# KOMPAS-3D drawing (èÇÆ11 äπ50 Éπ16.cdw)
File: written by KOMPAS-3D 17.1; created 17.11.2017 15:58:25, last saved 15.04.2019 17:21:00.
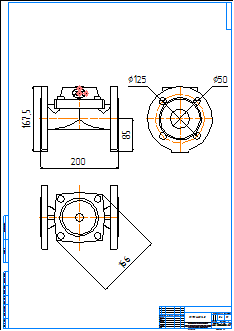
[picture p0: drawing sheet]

Sheet 1: A1, portrait

Title block, sheet 1: name: КАТ11 Ду50 Ру16; material: Внимание! Данный продукт является объектом авторского права ООО «Торговый Дом АДЛ». / Запрещается изменение, копирование, распространение / (в том числе путем копирования на другие сайты и ресурсы в Интернете) / или любое иное использование информации и объектов без предварительного / согласия правообладателя (ООО «Торговый Дом АДЛ»).; mass: 12,4; sheets: 1; organisation: ООО "Торговый дом АДЛ"; sheet format: A1; stored path: \\adlc.lan\data\АДЛ_ПКД\3D-модели\ADL production\Клапаны КАТ ГРАНРЕГ\КАТ11\KOMPAS 2D\КАТ11 Ду50 Ру16.cdw

Views: Вид 1, Проекционный вид 2, Проекционный вид 3
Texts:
  kka
  adl
Dimensions and other numbers on the sheet: 200; 85; 167,5; 125; 50; 166; 1:1; 1; 12,4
